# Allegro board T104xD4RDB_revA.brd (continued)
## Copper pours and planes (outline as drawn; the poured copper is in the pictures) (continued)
5V0_SLP on TOP (solid shape): 35.94,54.48 35.94,53.59 36.1,53.43 36.1,53.37 36.16,53.37 36.2,53.34 36.58,53.34 36.96,52.96 36.96,50.93 36.7,50.67 34.67,50.67 34.54,50.8 34.54,54.23 34.93,54.61 35.81,54.61
5V0_SLP on TOP (solid shape): 37.47,65.66 37.47,64.77 37.63,64.61 37.63,64.55 37.69,64.55 37.73,64.52 38.11,64.52 38.49,64.13 38.49,62.1 38.23,61.85 36.2,61.85 36.08,61.98 36.08,65.41 36.46,65.79 37.35,65.79
5V0_SLP on TOP (solid shape): 187.7,144.4 187.7,140.97 187.32,140.59 186.43,140.59 186.3,140.72 186.3,141.6 186.14,141.76 186.14,141.83 186.08,141.83 186.05,141.86 185.67,141.86 185.29,142.24 185.29,144.27 185.54,144.53 187.57,144.53
5V0_SLP on TOP (solid shape): 247.26,88.65 247.26,85.22 246.88,84.84 245.99,84.84 245.86,84.96 245.86,85.85 245.71,86.01 245.71,86.07 245.64,86.07 245.61,86.11 245.23,86.11 244.85,86.49 244.85,88.52 245.1,88.77 247.13,88.77
5V0_SLP on TOP (solid shape): 249.56,74.03 249.56,73.14 249.43,73.02 248.54,73.02 248.38,72.86 248.32,72.86 248.32,72.8 248.29,72.76 248.29,72.38 247.9,72 245.87,72 245.62,72.26 245.62,74.29 245.75,74.41 249.17,74.41
5V0_SLP on BOTTOM (solid shape): 30.94,165.76 30.94,165.23 30.98,165.01 31.12,164.82 31.12,162.06 30.86,161.81 29.97,161.81 29.46,161.3 29.46,159.9 29.08,159.52 26.54,159.52 26.29,159.77 26.29,161.63 26.68,161.79 26.85,162.19 26.85,165.51 27.41,166.07 30.63,166.07
5V0_SLP on BOTTOM (solid shape): 34.11,55.2 34.29,54.83 34.67,54.69 38,54.69 38.56,54.12 38.56,50.9 38.25,50.6 37.72,50.6 37.5,50.55 37.31,50.42 34.54,50.42 34.29,50.67 34.29,51.56 33.78,52.07 32.39,52.07 32,52.45 32,54.99 32.26,55.24 34.11,55.24
5V0_SLP on BOTTOM (solid shape): 35.64,66.37 35.82,66.01 36.2,65.86 39.53,65.86 40.09,65.3 40.09,62.08 39.78,61.77 39.25,61.77 39.03,61.73 38.84,61.59 36.08,61.59 35.82,61.85 35.82,62.74 35.31,63.25 33.92,63.25 33.54,63.63 33.54,66.17 33.79,66.42 35.64,66.42
5V0_SLP on BOTTOM (solid shape): 187.95,144.53 187.95,143.64 188.46,143.13 189.86,143.13 190.24,142.75 190.24,140.21 189.98,139.95 188.13,139.95 188.13,140 187.95,140.37 187.57,140.51 184.25,140.51 183.69,141.07 183.69,144.29 183.99,144.6 184.52,144.6 184.75,144.65 184.93,144.78 187.7,144.78
5V0_SLP on BOTTOM (solid shape): outline of 672 points within 199.77,70.4 261.37,147.32
5V0_SLP on TOP: 64.14,37.21 64.9,37.21 65.15,36.96 65.15,35.56 64.64,35.05 63.37,35.05 63.25,35.18 63.25,35.81 64.01,36.58 64.01,37.08
5V0_SLP on TOP: 5.59,50.8 8.89,50.8 9.53,50.16 9.53,40.64 8,39.12 6.6,39.12 6.48,39.24 6.48,40.89 5.08,42.29 5.08,50.29
5V0_SLP on TOP: 70.49,101.85 71.37,101.85 71.5,101.73 71.5,100.84 71.76,100.58 72.14,100.58 72.52,100.2 72.52,98.17 72.26,97.92 70.23,97.92 70.1,98.04 70.1,101.47
5V0_SLP on TOP: 33.4,36.32 36.7,36.32 36.96,36.58 36.96,44.07 36.45,44.58 33.4,44.58 33.15,44.32 33.15,36.58
5V0_SLP on TOP: 58.42,36.7 60.58,36.7 61.47,35.81 61.47,35.18 61.34,35.05 58.55,35.05 58.17,35.43 58.17,36.45
5V0_SLP on TOP: 20.83,72.39 21.46,71.75 21.46,60.33 20.7,59.56 11.81,59.56 11.18,60.2 11.18,71.88 11.68,72.39
5V0_SLP on BOTTOM: 6.35,42.67 20.32,42.67 20.96,43.31 20.96,71.5 20.32,72.14 6.48,72.14 6.1,71.75 6.1,42.93
5V0_SLP on BOTTOM: 67.82,102.49 69.6,102.49 70.1,101.98 73.03,101.98 74.17,100.84 74.17,98.17 73.66,97.66 70.23,97.66 69.85,98.04 69.85,98.93 69.47,99.31 67.95,99.31 67.56,99.69 67.56,102.23
5V0_SLP on L5PWR: 49.28,67.69 49.28,59.82 49.02,59.56 12.32,59.56 11.18,60.71 11.18,100.46 14.35,103.63 70.49,103.63 73.41,100.71 73.41,91.82
5V0_SLP on L6SIG: 20.83,72.64 37.47,72.64 40.26,69.85 40.26,48.01 41.53,46.74 49.34,46.74 55.44,40.64 64.26,40.64 67.82,37.08 67.82,27.56 72.64,22.73 72.64,19.05 72.01,18.42 64.01,18.42 59.44,22.99 59.44,33.27 57.91,34.8 54.1,34.8 48.01,40.89 6.48,40.89 5.08,42.29 5.08,164.21 29.72,188.85 201.42,188.85 206.5,183.77 206.5,146.69 205.36,145.54 192.47,145.54 190.31,143.38 190.31,139.83 189.55,139.06 184.28,139.06 183.64,139.7 183.64,148.72 185.8,150.88 191.71,150.88 195.58,154.75 195.58,172.85 191.9,176.53 50.67,176.53 42.16,168.02 42.16,163.7 19.3,140.84 19.3,74.17
5V0_SLP on L6SIG: 238.76,71.5 253.37,71.5 253.87,72.01 253.87,95.25 253.49,95.63 238.76,95.63 238.51,95.38 238.51,71.75
5V0_USB1 on TOP: 63.37,32.77 66.8,32.77 67.5,32.07 67.5,30.48 68.45,29.53 68.45,24 67.56,23.11 67.56,20.19 67.44,20.07 66.17,20.07 66.04,20.19 66.04,24.89 65.53,25.4 64.77,25.4 64.39,25.78 64.39,30.73 63.25,31.88 63.25,32.64
5V0_USB2 on TOP: 61.34,32.77 61.47,32.64 61.47,32 60.96,31.5 60.2,31.5 59.94,31.24 59.94,27.43 60.64,26.73 62.55,26.73 63.63,25.65 63.63,22.22 63.88,21.97 65.15,21.97 65.53,21.59 65.53,20.45 65.28,20.19 60.96,20.19 58.55,22.61 57.79,22.61 57.15,23.24 57.15,25.65 57.59,26.1 58.48,26.1 58.93,26.54 58.93,31.88 59.82,32.77
12V on TOP: 18.29,40.64 19.18,40.64 19.49,40.96 19.49,43.37 19.69,43.56 20.96,43.56 21.08,43.43 21.08,40.89 21.34,40.64 22.61,40.64 24.64,38.61 27.94,38.61 28.32,38.23 28.32,35.31 27.94,34.92 23.37,34.92 22.86,35.43 22.86,37.72 22.23,38.35 18.42,38.35 18.03,38.73 18.03,40.39
12V on TOP: 272.54,156.72 271.91,157.35 267.34,157.35 266.95,157.73 266.95,159.13 267.08,159.26 274.45,159.26 275.08,158.62 275.08,156.84 274.96,156.72
12V on TOP: 280.8,84.07 281.81,84.07 282.19,83.69 282.19,80.9 280.42,79.12 280.42,76.84 280.16,76.58 278.26,76.58 278,76.84 278,77.22 277.88,77.34 273.43,77.34 271.02,74.93 269.75,74.93 269.37,75.31 269.37,83.44 270,84.07 274.96,84.07 275.97,85.09 279.78,85.09
12V on TOP: 254.25,170.94 254.25,206.38 254.76,206.88 258.06,206.88 258.57,206.38 258.57,170.69 258.32,170.43 254.76,170.43
12V on BOTTOM: 21.84,37.97 23.5,36.32 26.42,36.32 26.92,36.83 26.92,76.84 21.21,82.55 21.21,173.86 35.05,187.71 249.3,187.71 254.25,182.75 254.25,167.39 265.68,155.96 265.68,85.22 271.78,79.12 282.07,79.12 282.96,80.01 282.96,84.33 282.7,84.58 280.8,84.58 280.42,84.96 276.73,84.96 275.46,86.23 274.19,86.23 273.3,87.12 273.3,157.73 260.86,170.18 260.86,187.71 252.86,195.71 30.73,195.71 14.99,179.96 14.99,80.52 21.84,73.66
12V_SLP on TOP: 61.47,82.55 61.6,82.68 62.23,82.68 62.48,82.93 62.48,83.57 62.36,83.69 60.33,83.69 60.07,83.44 60.07,81.66 60.2,81.53 61.34,81.53 61.47,81.66
12V_SLP on TOP: 25.65,49.02 27.94,46.74 27.94,40.39 27.69,40.13 24.89,40.13 24.64,40.39 24.64,42.55 23.24,43.94 16.76,43.94 15.88,43.05 12.19,43.05 11.68,43.56 11.68,46.74 12.45,47.5 14.61,47.5 16.13,49.02
12V_SLP on L3SIG: 26.54,44.45 26.54,41.91 26.92,41.53 39.24,41.53 40.01,42.29 54.1,42.29 58.17,46.35 58.17,77.72 61.98,81.53 61.98,82.8 61.6,83.19 58.42,83.19 55.25,80.01 55.25,66.55 53.59,64.9 53.59,63.37 55.12,61.85 55.12,57.15 52.58,54.61 52.58,47.24 49.78,44.45 40.13,44.45 39.37,45.21 27.31,45.21
12V_SLP on L6SIG: 60.2,82.93 61.47,82.93 61.72,82.68 61.72,81.79 61.34,81.41 60.58,81.41 60.07,81.91 60.07,82.8
AGND_SD1_PLL1 on L6SIG: 151.38,114.05 153.42,114.05 153.54,113.92 153.54,113.41 153.42,113.28 151.51,113.28 148.21,109.98 148.21,106.17 146.43,104.39 140.46,104.39 140.21,104.14 140.21,104.01 140.08,103.89 139.7,103.89 139.57,104.01 139.57,104.52 140.08,105.03 146.05,105.03 147.57,106.55 147.57,110.24
AGND_SD1_PLL2 on L6SIG: 152.4,117.86 153.42,117.86 153.54,117.73 153.54,117.22 153.42,117.09 152.53,117.09 146.56,111.12 146.56,107.7 146.05,107.19 144.02,107.19 143.64,107.57 141.16,107.57 141.03,107.7 140.53,107.7 140.34,107.51 140.34,107.31 140.21,107.19 139.83,107.19 139.7,107.31 139.7,107.7 140.08,108.08 145.67,108.08 145.92,108.33 145.92,111.38
AVDD_CGA1 on L5PWR: 122.81,99.95 127.25,99.95 127.51,99.69 128.14,99.69 128.27,99.57 128.27,99.19 128.14,99.06 127.64,99.06 127.25,98.68 126.24,98.68 125.48,97.92 122.81,97.92 122.56,98.17 122.56,99.69
AVDD_CGA2 on L5PWR: 122.68,101.6 128.02,101.6 128.27,101.35 128.27,100.08 128.14,99.95 127.64,99.95 127.38,100.2 122.81,100.2 122.56,100.46 122.56,101.47
AVDD_PLAT on L5PWR: 122.81,97.66 125.48,97.66 126.24,98.42 127.25,98.42 127.76,98.93 128.14,98.93 128.27,98.81 128.27,98.55 125.22,95.5 122.94,95.5 122.56,95.89 122.56,97.41
AVDD_SD1_PLL1 on L6SIG: 151.51,113.03 153.42,113.03 153.54,112.9 153.54,112.39 153.42,112.27 151.64,112.27 148.97,109.6 148.97,105.66 146.94,103.63 140.72,103.63 140.46,103.89 140.46,104.2 140.59,104.33 141.03,104.33 141.22,104.14 143.51,104.14 143.64,104.27 146.56,104.27 148.34,106.05 148.34,109.86
AVDD_SD1_PLL2 on L6SIG: 152.53,116.84 153.42,116.84 153.54,116.71 153.54,116.2 153.42,116.08 152.65,116.08 147.32,110.74 147.32,106.93 146.69,106.3 143.76,106.3 143.26,106.81 140.72,106.81 140.46,107.06 140.46,107.44 140.59,107.57 140.97,107.57 141.22,107.31 143.64,107.31 143.89,107.06 146.18,107.06 146.69,107.57 146.69,111
GND on TOP (solid shape): 178.69,89.66 178.69,86.11 178.44,85.85 177.91,85.85 177.67,85.9 177.44,85.85 176.91,85.85 176.66,86.11 176.66,89.53 176.91,89.79 178.56,89.79
GND on TOP (solid shape): 210.44,89.66 210.44,86.11 210.19,85.85 209.66,85.85 209.42,85.9 209.19,85.85 208.66,85.85 208.41,86.11 208.41,89.53 208.66,89.79 210.31,89.79
GND on TOP (solid shape): 42.93,55.24 42.93,46.1 42.16,45.34 35.05,45.34 34.64,45.75 34.64,46.83 34.54,46.83 34.54,48.13 34.67,48.26 36.96,48.26 37.72,47.5 40.51,47.5 41.02,48.01 41.02,51.56 40.51,52.07 37.72,52.07 37.47,52.32 37.47,52.96 36.83,53.59 36.75,53.59 36.7,53.65 36.4,53.65 36.32,53.72 36.32,54.99 36.96,55.63 42.55,55.63
GND on TOP (solid shape): 44.46,65.52 44.46,57.28 43.7,56.52 36.58,56.52 36.17,56.93 36.17,58.01 36.08,58.01 36.08,59.31 36.2,59.44 38.49,59.44 39.25,58.67 42.04,58.67 42.55,59.18 42.55,62.74 42.04,63.25 39.25,63.25 39,63.5 39,64.13 38.36,64.77 38.28,64.77 38.23,64.82 37.93,64.82 37.85,64.9 37.85,65.66 37.97,65.78 37.97,65.79 38.1,65.91 44.07,65.91
GND on TOP (solid shape): 187.6,149.45 187.6,148.37 187.7,148.37 187.7,147.07 187.57,146.94 185.29,146.94 184.52,147.7 181.73,147.7 181.22,147.19 181.22,143.64 181.73,143.13 184.52,143.13 184.78,142.88 184.78,142.24 185.41,141.6 185.49,141.6 185.54,141.55 185.85,141.55 185.92,141.48 185.92,140.72 185.8,140.6 185.8,140.59 185.67,140.46 179.71,140.46 179.32,140.85 179.32,149.1 180.08,149.86 187.19,149.86
GND on TOP (solid shape): 243.21,74.29 243.21,72 242.44,71.24 242.44,68.45 242.95,67.94 246.51,67.94 247.02,68.45 247.02,71.24 247.27,71.49 247.9,71.49 248.54,72.13 248.54,72.21 248.59,72.26 248.59,72.56 248.67,72.64 249.43,72.64 249.55,72.52 249.56,72.52 249.68,72.39 249.68,66.42 249.29,66.03 241.05,66.03 240.28,66.79 240.28,73.91 240.7,74.32 241.78,74.32 241.78,74.41 243.08,74.41
GND on TOP (solid shape): 247.17,93.69 247.17,92.62 247.26,92.62 247.26,91.31 247.13,91.19 244.85,91.19 244.09,91.95 241.29,91.95 240.78,91.44 240.78,87.88 241.29,87.38 244.09,87.38 244.34,87.12 244.34,86.49 244.98,85.85 245.05,85.85 245.1,85.8 245.41,85.8 245.48,85.72 245.48,84.96 245.36,84.84 245.36,84.84 245.24,84.71 239.27,84.71 238.88,85.1 238.88,93.34 239.64,94.11 246.75,94.11
GND on TOP (solid shape): outline of 256 points within 4.02,199.02 13.02,208.02
GND on TOP (solid shape): outline of 256 points within 4.02,11.52 13.02,20.52
GND on TOP (solid shape): outline of 256 points within 85.54,136.22 94.54,145.22
GND on TOP (solid shape): outline of 256 points within 139.02,199.02 148.02,208.02
GND on TOP (solid shape): outline of 256 points within 154,55.57 163,64.57
GND on TOP (solid shape): outline of 256 points within 274.02,199.02 283.02,208.02
GND on TOP (solid shape): outline of 256 points within 274.02,108.52 283.02,117.52
GND on BOTTOM (solid shape): 31.12,55.24 31.12,52.96 30.86,52.7 29.62,52.7 29.57,52.76 29.03,52.76 28.83,52.96 28.83,55.24 29.08,55.5 30.86,55.5
GND on BOTTOM (solid shape): 153.8,43.05 153.8,42.29 153.95,42.13 153.95,42.12 153.97,42.12 154.31,41.78 154.31,40.51 154.05,40.26 152.27,40.26 151.89,40.64 151.89,42.8 152.27,43.18 153.67,43.18
GND on BOTTOM (solid shape): 239.4,44.96 239.4,44.2 239.55,44.04 239.55,44.02 239.57,44.02 239.9,43.69 239.9,42.42 239.65,42.16 237.87,42.16 237.49,42.55 237.49,44.7 237.87,45.09 239.27,45.09
GND on BOTTOM (solid shape): 262.25,44.96 262.25,44.2 262.41,44.04 262.41,44.02 262.43,44.02 262.76,43.69 262.76,42.42 262.51,42.16 260.73,42.16 260.35,42.55 260.35,44.7 260.73,45.09 262.13,45.09
GND on BOTTOM (solid shape): 33.53,161.17 33.53,160.54 33.4,160.41 32.89,160.41 32.81,160.33 32.8,160.33 32.8,160.31 32.64,160.15 32.64,159.65 32.51,159.52 30.1,159.52 29.97,159.65 29.97,161.04 30.23,161.3 33.4,161.3
GND on BOTTOM (solid shape): 33.78,51.31 33.78,48.13 33.66,48.01 33.02,48.01 32.89,48.13 32.89,48.64 32.81,48.72 32.81,48.74 32.8,48.74 32.64,48.9 32.13,48.9 32,49.02 32,51.44 32.13,51.56 33.53,51.56
GND on BOTTOM (solid shape): 35.31,62.48 35.31,59.31 35.19,59.18 34.55,59.18 34.42,59.31 34.42,59.82 34.34,59.9 34.34,59.91 34.33,59.91 34.17,60.07 33.66,60.07 33.54,60.2 33.54,62.61 33.66,62.74 35.06,62.74
GND on BOTTOM (solid shape): 189.35,147.07 189.35,146.56 189.43,146.48 189.43,146.46 189.45,146.46 189.6,146.3 190.11,146.3 190.24,146.18 190.24,143.76 190.11,143.64 188.71,143.64 188.46,143.89 188.46,147.07 188.59,147.19 189.22,147.19
GND on BOTTOM (solid shape): 246.51,76.83 246.51,75.43 246.25,75.18 243.08,75.18 242.95,75.3 242.95,75.94 243.08,76.07 243.59,76.07 243.67,76.15 243.68,76.15 243.68,76.16 243.84,76.32 243.84,76.83 243.97,76.95 246.38,76.95
GND on BOTTOM (solid shape): 248.91,91.31 248.91,90.81 248.99,90.73 248.99,90.71 249.01,90.71 249.17,90.55 249.67,90.55 249.8,90.42 249.8,88.01 249.67,87.88 248.28,87.88 248.02,88.14 248.02,91.31 248.15,91.44 248.79,91.44
GND on BOTTOM (solid shape): 35.81,170.7 35.81,162.57 34.93,161.68 32.39,161.68 32.13,161.93 32.13,166.12 32.06,166.2 32.06,166.23 31.09,167.19 31.06,167.19 30.99,167.27 27.17,167.27 26.8,167.64 26.8,170.81 27.06,171.08 35.43,171.08
GND on BOTTOM (solid shape): 43.56,55.37 43.56,46.1 43.18,45.72 35.05,45.72 34.16,46.61 34.16,49.15 34.42,49.4 38.61,49.4 38.68,49.48 38.71,49.48 39.68,50.44 39.68,50.47 39.75,50.55 39.75,54.99 40.39,55.63 43.31,55.63
GND on BOTTOM (solid shape): 244.35,74.54 244.35,70.35 244.42,70.28 244.42,70.25 245.39,69.28 245.42,69.28 245.49,69.21 249.31,69.21 249.68,68.83 249.68,65.66 249.42,65.4 241.05,65.4 240.67,65.78 240.67,73.91 241.55,74.8 244.09,74.8
GND on BOTTOM (solid shape): 45.09,65.66 45.09,65.66 45.09,57.28 44.71,56.9 36.58,56.9 35.69,57.78 35.69,60.33 35.95,60.58 40.14,60.58 40.22,60.65 40.24,60.65 41.21,61.62 41.21,61.65 41.28,61.72 41.28,65.54 41.66,65.91 44.83,65.91
GND on BOTTOM (solid shape): 188.08,148.59 188.08,146.05 187.83,145.8 183.63,145.8 183.56,145.72 183.53,145.72 182.57,144.76 182.57,144.73 182.49,144.65 182.49,140.84 182.12,140.46 178.94,140.46 178.69,140.72 178.68,140.72 178.68,149.1 179.06,149.48 187.19,149.48
GND on BOTTOM (solid shape): 247.64,92.84 247.64,90.3 247.39,90.04 243.2,90.04 243.12,89.97 243.09,89.97 242.13,89 242.13,88.98 242.05,88.9 242.05,85.08 241.68,84.71 238.51,84.71 238.25,84.96 238.24,84.96 238.24,93.34 238.63,93.73 246.75,93.73
GND on BOTTOM (solid shape): 163.7,52.45 166.37,52.45 166.75,52.07 166.75,47.75 168.15,46.35 168.15,45.47 167.89,45.21 158.12,45.21 157.96,45.37 157.96,45.64 157.69,45.64 157.35,45.97 157.35,46.86 157.61,47.12 157.82,47.12 157.83,47.08 158.23,46.7 158.76,46.85 158.95,47.04 158.95,47.32 158.97,47.32 158.97,47.34 159.13,47.5 159.13,48.74 159.56,49.17 159.56,50.68 159.13,51.11 159.13,53.21 159.2,53.28 162.87,53.28
GND on BOTTOM (solid shape): 249.3,54.36 251.97,54.36 252.35,53.98 252.35,49.66 253.75,48.26 253.75,47.37 253.49,47.12 243.71,47.12 243.56,47.27 243.56,47.55 243.28,47.55 242.95,47.88 242.95,48.77 243.21,49.02 243.42,49.02 243.43,48.99 243.83,48.61 244.36,48.75 244.55,48.94 244.55,49.23 244.57,49.23 244.57,49.25 244.73,49.4 244.73,50.64 245.16,51.08 245.16,52.58 244.73,53.01 244.73,55.12 244.8,55.19 248.47,55.19
GND on BOTTOM (solid shape): 272.16,54.36 274.83,54.36 275.21,53.98 275.21,49.66 276.61,48.26 276.61,47.37 276.35,47.12 266.57,47.12 266.42,47.27 266.42,47.55 266.14,47.55 265.81,47.88 265.81,48.77 266.07,49.02 266.28,49.02 266.29,48.99 266.69,48.61 267.22,48.75 267.41,48.94 267.41,49.23 267.43,49.23 267.43,49.25 267.59,49.4 267.59,50.64 268.02,51.08 268.02,52.58 267.59,53.01 267.59,55.12 267.66,55.19 271.33,55.19
GND on BOTTOM (solid shape): outline of 256 points within 4.02,199.02 13.02,208.02
GND on BOTTOM (solid shape): outline of 256 points within 4.02,11.52 13.02,20.52
GND on BOTTOM (solid shape): outline of 256 points within 85.54,136.22 94.54,145.22
GND on BOTTOM (solid shape): outline of 256 points within 139.02,199.02 148.02,208.02
GND on BOTTOM (solid shape): outline of 256 points within 154,55.57 163,64.57
GND on BOTTOM (solid shape): outline of 256 points within 274.02,199.02 283.02,208.02
GND on BOTTOM (solid shape): outline of 256 points within 274.02,108.52 283.02,117.52
GND on BOTTOM (solid shape): outline of 424 points within 181.36,80.52 192.41,90.93
GND on BOTTOM (solid shape): outline of 424 points within 213.11,80.52 224.16,90.93
GND on TOP: 60.45,31.11 63.25,31.11 63.63,30.73 63.63,27.43 63.37,27.18 60.96,27.18 60.33,27.81 60.33,30.99
GND on TOP: 129.92,174.62 129.67,174.37 126.11,174.37 125.98,174.5 125.98,176.28 126.24,176.53 129.67,176.53 129.92,176.28
GND on TOP: outline of 135 points within 2.03,2.03 285,210
GND on TOP: 122.94,168.91 123.19,168.66 124.71,168.66 124.84,168.78 124.84,170.94 124.46,171.32 124.46,175.39 124.33,175.51 123.06,175.51 122.94,175.39
GND on TOP: 20.7,37.59 22.1,37.59 22.35,37.34 22.35,35.56 22.1,35.31 20.7,35.31 20.45,35.56 20.45,37.34
GND on TOP: 25.91,16.13 29.34,16.13 29.59,16.38 29.59,20.07 29.34,20.32 25.91,20.32 25.65,20.07 25.65,16.38
GND on TOP: 168.15,127.25 168.15,120.02 168.28,119.89 169.16,119.89 169.55,120.27 169.55,122.43 170.18,123.06 170.18,127.25 169.93,127.51 168.4,127.51
GND on TOP: 189.87,150.75 189.61,151 189.61,151.64 190.12,152.15 190.12,155.19 190.75,155.83 190.75,156.97 190.5,157.23 188.09,157.23 187.83,157.48 187.83,158.62 187.71,158.75 185.8,158.75 185.55,158.5 185.55,156.21 185.8,155.96 187.45,155.96 187.58,155.83 187.58,155.32 187.45,155.19 185.8,155.19 185.55,154.94 185.55,151.26 185.17,150.88 180.09,150.88 179.58,151.38 179.58,158.24 181.48,160.15 188.09,160.15 188.34,159.89 188.34,157.99 188.47,157.86 190.37,157.86 190.63,158.12 190.63,161.42 190.88,161.67 192.79,161.67 193.04,161.42 193.04,151.26 192.53,150.75
GND on TOP: 128.02,172.34 130.68,172.34 130.94,172.08 130.94,171.07 130.81,170.94 130.3,170.94 130.05,170.69 130.05,170.05 129.79,169.8 128.91,169.8 128.78,169.93 128.78,171.07 128.52,171.32 128.02,171.32 127.89,171.45 127.89,172.21
GND on TOP: 54.61,16.64 57.91,16.64 58.17,16.89 58.17,20.7 57.91,20.95 54.61,20.95 54.36,20.7 54.36,16.89
GND on TOP: 170.18,118.62 175.39,118.62 175.64,118.36 175.64,116.71 175.39,116.46 170.18,116.46 169.93,116.71 169.93,118.36
GND on TOP: 269.88,157.1 270.13,156.84 270.13,155.96 270.38,155.7 270.38,153.03 270.26,152.91 268.86,152.91 268.61,153.16 268.61,154.69 268.48,154.81 267.84,154.81 267.59,155.07 267.59,156.84 267.84,157.1
GND on TOP: 118.49,31.37 118.49,21.21 118.11,20.83 116.21,20.83 116.08,20.95 116.08,31.37 116.33,31.62 118.24,31.62
GND on TOP: 18.8,43.18 19.05,42.93 19.05,41.27 18.92,41.15 16.89,41.15 16.64,41.4 16.64,42.93 16.89,43.18
GND on TOP: 92.84,87.25 92.58,87.5 92.58,101.47 92.08,101.98 83.95,101.98 83.31,101.35 83.31,91.95 82.8,91.44 70.99,91.44 70.23,92.2 70.23,95.38 70.36,95.5 72.64,95.5 74.17,93.98 77.98,93.98 78.36,94.36 78.36,99.69 77.98,100.08 73.28,100.08 72.39,100.97 72.01,100.97 71.88,101.09 71.88,104.65 72.26,105.03 87.5,105.03 88.9,103.63 90.68,103.63 90.93,103.89 90.93,104.65 91.06,104.78 93.35,104.78 94.23,103.89 95,103.89 96.77,102.11 96.77,96.39 97.03,96.14 100.08,96.14 100.33,96.39 100.33,102.62 103.12,102.62 104.01,101.73 104.01,88.39 102.87,87.25
GND on TOP: 58.42,34.67 63.5,34.67 63.63,34.54 63.63,33.27 63.5,33.15 58.42,33.15 58.29,33.27 58.29,34.54
GND on TOP: 33.15,162.31 33.15,164.6 33.91,165.36 33.91,168.16 33.4,168.66 29.85,168.66 29.34,168.16 29.34,165.36 29.08,165.11 28.45,165.11 27.81,164.47 27.81,164.09 27.69,163.96 26.92,163.96 26.8,164.08 26.8,164.08 26.67,164.21 26.67,170.18 27.06,170.57 35.31,170.57 36.07,169.81 36.07,162.69 35.56,162.19 33.27,162.19
GND on TOP: 239.4,59.82 241.55,59.82 241.81,59.56 241.81,57.53 241.55,57.28 239.52,57.28 239.27,57.53 239.27,59.69
GND on TOP: 270.13,93.73 271.14,93.73 271.53,93.34 271.53,92.58 271.91,92.2 271.91,89.53 271.78,89.41 270.38,89.41 270,89.79 270,93.6
GND on TOP: 69.6,25.65 73.41,25.65 73.66,25.91 73.66,29.34 73.41,29.59 69.6,29.59 69.34,29.34 69.34,25.91
GND on BOTTOM: 45.34,134.87 79.63,134.87 79.88,134.62 79.88,133.22 79.63,132.97 45.47,132.97 45.21,133.22 45.21,134.75
GND on BOTTOM: 93.22,100.84 93.98,101.6 95.12,101.6 95.25,101.47 95.25,96.14 95.76,95.63 100.84,95.63 101.35,96.14 101.35,107.7 101.6,107.95 103.51,107.95 103.89,107.57 103.89,84.58 102.74,83.44 97.16,83.44 96.9,83.69 96.9,91.31 96.52,91.69 94.36,91.69 93.22,92.84
GND on BOTTOM: 67.69,98.81 69.09,98.81 69.34,98.55 69.34,95.38 69.22,95.25 68.58,95.25 68.45,95.38 68.45,96.01 68.2,96.27 67.69,96.27 67.56,96.39 67.56,98.68
GND on BOTTOM: 3.52,2.03 2.47,2.47 2.03,3.52 2.03,208.52 2.47,209.57 3.52,210 283.52,210 284.57,209.57 285,208.52 285,88.53 283.46,87 275.59,87 274.07,88.52 274.07,157.99 261.62,170.43 261.62,187.83 253.11,196.34 30.23,196.34 14.22,180.34 14.22,80.39 14.99,79.63 14.99,73.79 14.1,72.9 5.46,72.9 4.7,72.14 4.7,24.51 6.99,22.22 12.83,22.22 15.37,19.69 20.96,19.69 23.5,22.22 56.9,22.22 57.91,21.21 57.91,2.79 57.15,2.03
GND on BOTTOM: 124.33,52.96 125.35,51.94 126.75,51.94 127.25,51.44 127.25,47.37 127,47.12 122.68,47.12 122.43,47.37 122.43,52.45 122.94,52.96
GND on BOTTOM: 160.15,118.87 160.15,112.27 160.4,112.01 161.29,112.01 161.42,112.14 161.42,118.87 161.29,119 160.27,119
GND on BOTTOM: 142.37,60.96 143.38,59.94 144.65,59.94 145.16,59.44 145.16,55.37 144.91,55.12 140.97,55.12 140.34,55.75 140.34,60.58 140.72,60.96
GND on BOTTOM: 237.11,132.33 241.17,132.33 241.43,132.08 241.43,127.38 241.3,127.25 241.05,127.25 240.92,127.38 240.92,127.63 240.79,127.76 237.49,127.76 237.11,128.14 237.11,130.05 236.86,130.3 236.86,132.08
GND on BOTTOM: 165.99,112.01 166.12,112.14 166.12,119 165.99,119.13 165.48,119.13 165.35,119 165.35,112.14 165.48,112.01
GND on BOTTOM: 60.96,106.81 86.11,106.81 86.61,106.3 86.61,92.58 85.22,91.19 61.85,91.19 60.45,92.58 60.45,106.3 ; 1 cut-out
GND on L2GND: 3.52,2.03 2.47,2.47 2.03,3.52 2.03,208.52 2.47,209.57 3.52,210 283.52,210 284.57,209.57 285,208.52 285,29.86 284.23,29.08 238.89,29.08 236.28,31.69 236.28,36.77 234.57,38.48 230.89,38.48 230.12,39.24 172.47,39.24 169.99,36.77 169.99,32.58 167.26,29.84 154.94,29.84 149.86,34.92 149.86,39.12 148.59,40.39 134.62,40.39 133.22,38.99 133.22,35.05 132.46,34.29 119.51,34.29 118.75,33.53 118.75,21.46 123.57,16.64 123.57,7.37 120.9,4.7 109.86,4.7 107.95,6.6 107.95,17.14 106.3,18.8 100.58,18.8 92.96,11.18 92.96,7.62 92.71,7.37 83.44,7.37 83.06,7.75 83.06,11.3 81.66,12.7 81.66,16.38 80.01,18.03 73.79,18.03 73.15,17.4 73.15,11.05 72.14,10.03 65.91,10.03 65.15,10.8 65.15,17.27 64.39,18.03 60.33,18.03 59.44,17.14 59.44,2.67 58.8,2.03 ; 30 cut-outs
GND on L4PWR: 3.52,2.03 2.47,2.47 2.03,3.52 2.03,208.52 2.47,209.57 3.52,210 283.52,210 284.57,209.57 285,208.52 285,29.86 284.23,29.08 238.89,29.08 236.28,31.69 236.28,36.77 234.57,38.48 230.89,38.48 230.12,39.24 172.47,39.24 169.99,36.77 169.99,32.58 167.26,29.84 154.94,29.84 149.86,34.92 149.86,39.12 148.59,40.39 134.62,40.39 133.22,38.99 133.22,35.05 132.46,34.29 119.51,34.29 118.75,33.53 118.75,21.46 123.57,16.64 123.57,7.37 120.9,4.7 109.86,4.7 107.95,6.6 107.95,17.14 106.3,18.8 100.58,18.8 92.96,11.18 92.96,7.62 92.71,7.37 83.44,7.37 83.06,7.75 83.06,11.3 81.66,12.7 81.66,16.38 80.01,18.03 73.79,18.03 73.15,17.4 73.15,11.05 72.14,10.03 66.04,10.03 65.15,10.92 65.15,17.27 64.39,18.03 60.33,18.03 59.44,17.14 59.44,2.67 58.8,2.03 ; 1 cut-out
GND on L5PWR: 3.52,2.03 2.47,2.47 2.03,3.52 2.03,208.52 2.47,209.57 3.52,210 283.52,210 284.57,209.57 285,208.52 285,29.86 284.23,29.08 238.89,29.08 235.59,32.39 235.59,54.86 233.93,56.52 173.1,56.52 170.05,53.47 170.05,32.64 167.26,29.84 154.94,29.84 149.86,34.92 149.86,39.12 148.59,40.39 134.62,40.39 133.22,38.99 133.22,35.05 132.46,34.29 119.51,34.29 118.75,33.53 118.75,21.46 123.57,16.64 123.57,7.37 120.9,4.7 109.86,4.7 107.95,6.6 107.95,17.14 106.3,18.8 100.58,18.8 92.96,11.18 92.96,7.62 92.71,7.37 83.44,7.37 83.06,7.75 83.06,11.3 81.66,12.7 81.66,16.38 80.01,18.03 73.79,18.03 73.15,17.4 73.15,11.05 72.14,10.03 66.04,10.03 65.15,10.92 65.15,17.27 64.39,18.03 60.33,18.03 59.44,17.14 59.44,2.67 58.8,2.03 ; 1 cut-out
GND on L7GND: 3.52,2.03 2.47,2.47 2.03,3.52 2.03,208.52 2.47,209.57 3.52,210 283.52,210 284.57,209.57 285,208.52 285,29.86 284.23,29.08 238.89,29.08 235.59,32.39 235.59,54.86 233.93,56.52 173.1,56.52 170.05,53.47 170.05,32.64 167.26,29.84 154.94,29.84 149.86,34.92 149.86,39.12 148.59,40.39 134.62,40.39 133.22,38.99 133.22,35.05 132.46,34.29 119.51,34.29 118.75,33.53 118.75,21.46 123.57,16.64 123.57,7.37 120.9,4.7 109.86,4.7 107.95,6.6 107.95,17.14 106.3,18.8 100.58,18.8 92.96,11.18 92.96,7.62 92.71,7.37 83.44,7.37 83.06,7.75 83.06,11.3 81.66,12.7 81.66,16.38 80.01,18.03 73.79,18.03 73.15,17.4 73.15,11.05 72.14,10.03 65.91,10.03 65.15,10.8 65.15,17.27 64.39,18.03 60.33,18.03 59.44,17.14 59.44,2.67 58.8,2.03
SVDD on BOTTOM: 161.93,114.94 161.93,112.27 162.05,112.14 164.97,112.14 165.1,112.27 165.1,114.81 164.85,115.06 162.05,115.06
SVDD on L4PWR: 138.68,108.46 140.21,108.46 140.46,108.2 140.46,100.84 140.34,100.71 139.19,100.71 138.94,100.97 138.94,102.36 138.18,103.12 138.18,107.95
SVDD on L5PWR: 138.43,108.2 139.45,108.2 139.7,107.95 139.7,103.38 139.45,103.12 138.3,103.12 138.18,103.25 138.18,107.95
SVDD on L6SIG: 137.16,107.95 138.94,107.95 139.07,107.82 139.07,103.38 139.32,103.12 147.57,103.12 149.73,105.28 149.73,108.97 152.4,111.63 154.05,111.63 154.56,112.14 154.56,114.55 155.32,115.32 164.21,115.32 164.47,115.06 164.47,107.82 156.34,99.69 137.41,99.69 137.03,100.08 137.03,107.82
(no net) on TOP: 235.32,94.11 235.07,93.85 235.07,84.97 235.33,84.71 237.99,84.71 238.37,85.09 238.37,93.73 237.99,94.11
(no net) on TOP: 262.64,45.21 264.92,45.21 265.43,45.72 266.19,45.72 266.19,45.21 265.05,44.07 262.64,44.07 262.51,44.2 262.51,45.09
(no net) on TOP: 210.95,89.79 212.34,89.79 212.6,89.53 212.6,86.11 212.34,85.85 210.95,85.85 210.82,85.98 210.82,89.66
(no net) on TOP: 49.66,56.52 50.55,57.4 50.55,61.34 50.29,61.59 48.52,61.59 48.27,61.85 48.27,65.65 48.01,65.91 45.35,65.91 44.97,65.53 44.97,56.9 45.35,56.52
(no net) on TOP: 26.04,122.05 27.81,122.05 28.07,121.79 28.07,119.76 27.94,119.63 26.16,119.63 25.91,119.89 25.91,121.92
(no net) on TOP: 176.91,89.79 178.56,89.79 178.69,89.66 178.69,86.11 178.44,85.85 176.91,85.85 176.66,86.11 176.66,89.53
(no net) on TOP: 179.2,89.79 180.59,89.79 180.85,89.53 180.85,86.11 180.59,85.85 179.2,85.85 179.07,85.98 179.07,89.66
(no net) on TOP: 41.79,59.18 39.5,59.18 38.87,59.82 36.08,59.82 35.95,59.94 35.95,61.34 36.08,61.47 38.74,61.47 40.01,62.74 41.79,62.74 42.04,62.48 42.04,59.44
(no net) on TOP: 243.21,74.29 243.21,72 242.44,71.24 242.44,68.45 242.95,67.94 246.51,67.94 247.02,68.45 247.02,71.24 247.27,71.49 247.9,71.49 248.54,72.13 248.54,72.51 248.67,72.64 249.43,72.64 249.55,72.52 249.56,72.52 249.68,72.39 249.68,66.42 249.29,66.03 241.05,66.03 240.28,66.79 240.28,73.91 240.79,74.41 243.08,74.41
(no net) on TOP: 36.2,59.44 38.49,59.44 39.25,58.67 42.04,58.67 42.55,59.18 42.55,62.74 42.04,63.25 39.25,63.25 39,63.5 39,64.13 38.36,64.77 37.98,64.77 37.85,64.9 37.85,65.66 37.97,65.78 37.97,65.79 38.1,65.91 44.07,65.91 44.46,65.52 44.46,57.28 43.7,56.52 36.58,56.52 36.08,57.02 36.08,59.31
(no net) on TOP: 242.95,68.7 242.95,70.99 243.59,71.62 243.59,74.41 243.71,74.54 245.11,74.54 245.24,74.41 245.24,71.75 246.51,70.48 246.51,68.7 246.25,68.45 243.21,68.45
(no net) on TOP: 40.26,48.01 37.97,48.01 37.34,48.64 34.54,48.64 34.42,48.77 34.42,50.16 34.54,50.29 37.21,50.29 38.48,51.56 40.26,51.56 40.51,51.31 40.51,48.26
(no net) on TOP: 264.54,43.31 261.37,43.31 261.24,43.18 261.24,42.16 261.75,41.66 264.41,41.66 264.67,41.91 264.67,43.18
(no net) on TOP: 240.28,62.48 240.54,62.22 252.34,62.22 252.6,62.48 252.6,64.9 251.97,65.53 251.73,65.53 251.72,65.52 240.67,65.52 240.28,65.14
(no net) on TOP: 33.53,167.77 33.53,165.49 32.89,164.85 32.89,162.06 32.77,161.93 31.37,161.93 31.24,162.06 31.24,164.73 29.97,166 29.97,167.77 30.23,168.03 33.27,168.03
(no net) on TOP: 26.04,130.18 27.81,130.18 28.07,129.92 28.07,127.89 27.94,127.76 26.16,127.76 25.91,128.02 25.91,130.05
(no net) on TOP: 154.18,43.31 156.46,43.31 156.97,43.81 157.73,43.81 157.73,43.31 156.59,42.16 154.18,42.16 154.05,42.29 154.05,43.18
(no net) on TOP: 171.32,149.86 170.94,149.48 170.94,144.65 171.58,144.02 173.61,144.02 173.99,143.64 173.99,141.1 174.62,140.46 178.43,140.46 178.81,140.84 178.81,149.48 178.43,149.86
(no net) on TOP: 36.2,174 35.94,174.25 27.06,174.25 26.8,173.99 26.8,171.33 27.18,170.95 35.81,170.95 36.2,171.33
(no net) on TOP: 241.55,91.44 243.83,91.44 244.47,90.81 247.26,90.81 247.39,90.68 247.39,89.28 247.26,89.15 244.59,89.15 243.32,87.88 241.55,87.88 241.29,88.14 241.29,91.19
(no net) on TOP: 28.58,119.63 32.64,119.63 32.89,119.89 32.89,121.79 32.64,122.05 28.7,122.05 28.45,121.79 28.45,119.76
(no net) on TOP: 50.29,45.34 51.05,46.1 51.05,51.44 50.8,51.69 47.12,51.69 46.74,52.07 46.74,55.12 46.23,55.63 43.82,55.63 43.43,55.24 43.43,45.72 43.82,45.34
(no net) on TOP: 34.67,48.26 36.96,48.26 37.72,47.5 40.51,47.5 41.02,48.01 41.02,51.56 40.51,52.07 37.72,52.07 37.47,52.32 37.47,52.96 36.83,53.59 36.45,53.59 36.32,53.72 36.32,54.99 36.96,55.63 42.55,55.63 42.93,55.24 42.93,46.1 42.16,45.34 35.05,45.34 34.54,45.85 34.54,48.13
(no net) on TOP: 181.98,147.19 184.27,147.19 184.9,146.56 187.7,146.56 187.83,146.43 187.83,145.03 187.7,144.91 185.03,144.91 183.76,143.64 181.98,143.64 181.73,143.89 181.73,146.94
(no net) on TOP: 28.58,127.76 32.64,127.76 32.89,128.02 32.89,129.92 32.64,130.18 28.7,130.18 28.45,129.92 28.45,127.89
(no net) on TOP: 187.57,146.94 185.29,146.94 184.52,147.7 181.73,147.7 181.22,147.19 181.22,143.64 181.73,143.13 184.52,143.13 184.78,142.88 184.78,142.24 185.41,141.6 185.79,141.6 185.92,141.48 185.92,140.72 185.8,140.6 185.8,140.59 185.67,140.46 179.71,140.46 179.32,140.85 179.32,149.1 180.08,149.86 187.19,149.86 187.7,149.35 187.7,147.07
(no net) on TOP: 247.13,91.19 244.85,91.19 244.09,91.95 241.29,91.95 240.78,91.44 240.78,87.88 241.29,87.38 244.09,87.38 244.34,87.12 244.34,86.49 244.98,85.85 245.36,85.85 245.48,85.72 245.48,84.96 245.36,84.84 245.36,84.84 245.24,84.71 239.27,84.71 238.88,85.1 238.88,93.34 239.64,94.11 246.75,94.11 247.26,93.6 247.26,91.31
(no net) on TOP: 26.04,138.3 27.81,138.3 28.07,138.05 28.07,136.02 27.94,135.89 26.16,135.89 25.91,136.14 25.91,138.18
(no net) on TOP: 181.36,91.57 181.48,91.44 181.48,90.42 181.36,90.3 177.55,90.3 177.42,90.42 177.42,91.44 177.55,91.57
(no net) on TOP: 36.2,61.85 38.23,61.85 38.49,62.1 38.49,64.13 38.11,64.52 37.73,64.52 37.47,64.77 37.47,65.66 37.35,65.79 36.46,65.79 36.08,65.41 36.08,61.98
(no net) on TOP: 239.78,45.21 242.06,45.21 242.57,45.72 243.33,45.72 243.33,45.21 242.19,44.07 239.78,44.07 239.65,44.2 239.65,45.09
(no net) on TOP: 28.58,135.89 32.64,135.89 32.89,136.14 32.89,138.05 32.64,138.3 28.7,138.3 28.45,138.05 28.45,136.02
(no net) on TOP: 241.68,43.31 238.51,43.31 238.38,43.18 238.38,42.16 238.89,41.66 241.55,41.66 241.81,41.91 241.81,43.18
(no net) on TOP: 247.13,88.77 245.1,88.77 244.85,88.52 244.85,86.49 245.23,86.11 245.61,86.11 245.86,85.85 245.86,84.96 245.99,84.84 246.88,84.84 247.26,85.22 247.26,88.65
(no net) on TOP: 156.08,41.4 152.91,41.4 152.78,41.27 152.78,40.26 153.29,39.75 155.96,39.75 156.21,40.01 156.21,41.27
(no net) on TOP: 187.57,144.53 185.54,144.53 185.29,144.27 185.29,142.24 185.67,141.86 186.05,141.86 186.3,141.6 186.3,140.72 186.43,140.59 187.32,140.59 187.7,140.97 187.7,144.4
(no net) on TOP: 213.11,91.57 213.23,91.44 213.23,90.42 213.11,90.3 209.3,90.3 209.17,90.42 209.17,91.44 209.3,91.57
(no net) on TOP: 34.67,50.67 36.7,50.67 36.96,50.93 36.96,52.96 36.58,53.34 36.2,53.34 35.94,53.59 35.94,54.48 35.81,54.61 34.93,54.61 34.54,54.23 34.54,50.8
(no net) on TOP: 30.86,162.19 30.86,164.22 30.61,164.47 28.58,164.47 28.19,164.09 28.19,163.71 27.94,163.46 27.05,163.46 26.92,163.33 26.92,162.44 27.31,162.06 30.73,162.06
(no net) on TOP: 208.66,89.79 210.31,89.79 210.44,89.66 210.44,86.11 210.19,85.85 208.66,85.85 208.41,86.11 208.41,89.53
(no net) on TOP: 245.62,74.29 245.62,72.26 245.87,72 247.9,72 248.29,72.38 248.29,72.76 248.54,73.02 249.43,73.02 249.56,73.14 249.56,74.03 249.17,74.41 245.75,74.41
(no net) on BOTTOM: 240.28,43.56 240.28,41.91 240.54,41.66 249.81,41.66 252.6,44.45 252.6,46.23 252.22,46.61 244.6,46.61 243.52,45.53 243.52,44.77 242.57,43.81 240.54,43.81
(no net) on BOTTOM: 182.49,140.84 182.49,144.65 183.63,145.8 187.83,145.8 188.08,146.05 188.08,148.59 187.19,149.48 179.06,149.48 178.68,149.1 178.68,140.72 178.69,140.72 178.94,140.46 182.12,140.46
(no net) on BOTTOM: 224.16,82.3 224.03,82.17 222.76,82.17 222.12,82.8 216.66,82.8 216.54,82.93 214.88,82.93 214.5,82.55 214.5,80.77 214.25,80.52 213.36,80.52 213.11,80.77 213.11,89.15 214.88,90.93 223.01,90.93 224.16,89.79
(no net) on BOTTOM: 239.27,45.09 239.4,44.96 239.4,44.2 239.9,43.69 239.9,42.42 239.65,42.16 237.87,42.16 237.49,42.55 237.49,44.7 237.87,45.09
(no net) on BOTTOM: 187.95,143.64 187.95,144.53 187.7,144.78 183.89,144.78 183.63,144.53 183.63,141.1 184.4,140.34 187.7,140.34 188.08,139.95 189.98,139.95 190.24,140.21 190.24,142.75 189.86,143.13 188.46,143.13
(no net) on BOTTOM: 29.97,161.81 30.86,161.81 31.12,162.06 31.12,165.87 30.86,166.12 27.43,166.12 26.67,165.36 26.67,162.06 26.29,161.68 26.29,159.77 26.54,159.52 29.08,159.52 29.46,159.9 29.46,161.3
(no net) on BOTTOM: 263.14,43.56 263.14,41.91 263.4,41.66 272.67,41.66 275.46,44.45 275.46,46.23 275.08,46.61 267.46,46.61 266.38,45.53 266.38,44.77 265.43,43.81 263.4,43.81
(no net) on BOTTOM: 33.53,161.17 33.53,160.54 33.4,160.41 32.89,160.41 32.64,160.15 32.64,159.65 32.51,159.52 30.1,159.52 29.97,159.65 29.97,161.04 30.23,161.3 33.4,161.3
(no net) on BOTTOM: 262.13,45.09 262.25,44.96 262.25,44.2 262.76,43.69 262.76,42.42 262.51,42.16 260.73,42.16 260.35,42.55 260.35,44.7 260.73,45.09
(no net) on BOTTOM: 237.36,93.73 235.32,93.73 234.94,93.34 234.94,84.96 234.95,84.96 235.2,84.71 237.48,84.71 237.74,84.96 237.74,93.34
(no net) on BOTTOM: 242.05,85.08 242.05,88.9 243.2,90.04 247.39,90.04 247.64,90.3 247.64,92.84 246.75,93.73 238.63,93.73 238.24,93.34 238.24,84.96 238.25,84.96 238.51,84.71 241.68,84.71
(no net) on BOTTOM: 242.95,75.3 242.95,75.94 243.08,76.07 243.59,76.07 243.84,76.32 243.84,76.83 243.97,76.95 246.38,76.95 246.51,76.83 246.51,75.43 246.25,75.18 243.08,75.18
(no net) on BOTTOM: 27.17,167.27 30.99,167.27 32.13,166.12 32.13,161.93 32.39,161.68 34.93,161.68 35.81,162.57 35.81,170.7 35.43,171.08 27.05,171.08 27.05,171.07 26.8,170.81 26.8,167.64
(no net) on BOTTOM: 44.45,45.72 46.48,45.72 46.86,46.1 46.86,55.24 46.48,55.63 44.32,55.63 44.07,55.37 44.07,46.1
(no net) on BOTTOM: 177.79,149.48 175.76,149.48 175.38,149.1 175.38,140.72 175.39,140.72 175.64,140.46 177.92,140.46 178.17,140.72 178.17,149.1
(no net) on BOTTOM: 33.66,48.01 33.02,48.01 32.89,48.13 32.89,48.64 32.64,48.9 32.13,48.9 32,49.02 32,51.44 32.13,51.56 33.53,51.56 33.78,51.31 33.78,48.13
(no net) on BOTTOM: 188.59,147.19 189.22,147.19 189.35,147.07 189.35,146.56 189.6,146.3 190.11,146.3 190.24,146.18 190.24,143.76 190.11,143.64 188.71,143.64 188.46,143.89 188.46,147.07
(no net) on BOTTOM: 153.67,43.18 153.8,43.05 153.8,42.29 154.31,41.78 154.31,40.51 154.05,40.26 152.27,40.26 151.89,40.64 151.89,42.8 152.27,43.18
(no net) on BOTTOM: 34.29,51.56 34.29,50.67 34.54,50.42 38.35,50.42 38.61,50.67 38.61,54.1 37.85,54.86 34.54,54.86 34.16,55.24 32.26,55.24 32,54.99 32,52.45 32.39,52.07 33.78,52.07
(no net) on BOTTOM: 192.41,82.3 192.28,82.17 191.01,82.17 190.37,82.8 184.91,82.8 184.79,82.93 183.13,82.93 182.75,82.55 182.75,80.77 182.5,80.52 181.61,80.52 181.36,80.77 181.36,89.15 183.13,90.93 191.26,90.93 192.41,89.79
(no net) on BOTTOM: 45.98,56.9 48.01,56.9 48.39,57.28 48.39,65.66 48.39,65.66 48.13,65.91 45.85,65.91 45.6,65.66 45.6,57.28
(no net) on BOTTOM: 249.31,69.21 245.49,69.21 244.35,70.35 244.35,74.54 244.09,74.8 241.55,74.8 240.67,73.91 240.67,65.78 241.05,65.4 249.43,65.4 249.43,65.41 249.68,65.66 249.68,68.83
(no net) on BOTTOM: 243.71,47.12 253.49,47.12 253.75,47.37 253.75,48.26 252.35,49.66 252.35,53.98 251.97,54.36 249.3,54.36 248.41,55.24 244.86,55.24 244.73,55.12 244.73,49.4 244.35,49.02 243.21,49.02 242.95,48.77 242.95,47.88
(no net) on BOTTOM: 245.62,70.35 245.36,70.6 245.36,74.41 245.62,74.67 246.51,74.67 247.02,75.18 247.02,76.57 247.4,76.95 247.4,76.96 247.71,77.28 247.71,84.13 247.26,84.58 243.96,84.58 243.2,85.34 243.2,88.77 243.45,89.03 247.26,89.03 247.52,88.77 247.52,87.88 248.02,87.38 249.42,87.38 250.06,86.74 253.24,86.74 253.75,87.25 253.75,104.39 243.97,114.17 225.43,114.17 217.68,121.92 204.22,121.92 199.77,126.36 199.77,146.94 200.15,147.32 205.87,147.32 206.88,146.3 206.88,131.57 210.19,128.27 222,128.27 228.47,121.79 248.29,121.79 261.37,108.71 261.37,82.93 253.24,74.8 250.19,74.8 250.19,74.8 249.81,74.41 249.81,71.11 249.05,70.35
(no net) on BOTTOM: 41.28,65.54 41.28,61.72 40.14,60.58 35.95,60.58 35.69,60.33 35.69,57.78 36.58,56.9 44.71,56.9 45.09,57.28 45.09,65.66 45.09,65.66 44.83,65.91 41.66,65.91
(no net) on BOTTOM: 35.81,171.97 35.81,174 35.43,174.38 27.05,174.38 27.05,174.37 26.8,174.12 26.8,171.84 27.05,171.58 35.43,171.58
(no net) on BOTTOM: 35.82,62.74 35.82,61.85 36.08,61.59 39.89,61.59 40.14,61.85 40.14,65.28 39.38,66.04 36.08,66.04 35.69,66.42 33.79,66.42 33.54,66.17 33.54,63.63 33.92,63.25 35.31,63.25
(no net) on BOTTOM: 248.15,91.44 248.79,91.44 248.91,91.31 248.91,90.81 249.17,90.55 249.67,90.55 249.8,90.42 249.8,88.01 249.67,87.88 248.28,87.88 248.02,88.14 248.02,91.31
(no net) on BOTTOM: 39.75,54.99 39.75,50.55 38.61,49.4 34.42,49.4 34.16,49.15 34.16,46.61 35.05,45.72 43.18,45.72 43.56,46.1 43.56,55.37 43.31,55.63 40.39,55.63
(no net) on BOTTOM: 35.19,59.18 34.55,59.18 34.42,59.31 34.42,59.82 34.17,60.07 33.66,60.07 33.54,60.2 33.54,62.61 33.66,62.74 35.06,62.74 35.31,62.48 35.31,59.31
(no net) on BOTTOM: 28.83,55.24 28.83,52.96 29.08,52.7 30.86,52.7 31.12,52.96 31.12,55.24 30.86,55.5 29.08,55.5
(no net) on BOTTOM: 154.69,41.66 154.69,40.01 154.94,39.75 164.21,39.75 167.01,42.55 167.01,44.32 166.62,44.7 159,44.7 157.92,43.62 157.92,42.86 156.97,41.91 154.94,41.91
(no net) on BOTTOM: 240.67,64.51 240.67,62.48 241.05,62.1 249.43,62.1 249.43,62.1 249.68,62.36 249.68,64.64 249.43,64.89 241.05,64.89
(no net) on BOTTOM: 266.57,47.12 276.35,47.12 276.61,47.37 276.61,48.26 275.21,49.66 275.21,53.98 274.83,54.36 272.16,54.36 271.27,55.24 267.72,55.24 267.59,55.12 267.59,49.4 267.21,49.02 266.07,49.02 265.81,48.77 265.81,47.88
(no net) on BOTTOM: 158.12,45.21 167.89,45.21 168.15,45.47 168.15,46.35 166.75,47.75 166.75,52.07 166.37,52.45 163.7,52.45 162.81,53.34 159.26,53.34 159.13,53.21 159.13,47.5 158.75,47.12 157.61,47.12 157.35,46.86 157.35,45.97
(no net) on L3SIG: 180.21,91.31 191.01,91.31 193.29,89.03 193.29,81.15 192.53,80.39 189.74,80.39 189.48,80.64 185.55,80.64 185.17,81.03 182.5,81.03 179.96,83.57 179.96,91.06
(no net) on L6SIG: 209.55,82.93 221.11,82.93 221.62,82.42 221.62,79.63 221.23,79.25 209.55,79.25 209.17,79.63 209.17,82.55
(no net) on L6SIG: 177.8,82.93 189.36,82.93 189.87,82.42 189.87,79.63 189.48,79.25 177.8,79.25 177.42,79.63 177.42,82.55
EARTH on TOP (solid shape): outline of 256 points within 274.02,4.02 283.02,13.02
EARTH on BOTTOM (solid shape): outline of 256 points within 274.02,4.02 283.02,13.02
EARTH on TOP: outline of 98 points within 60.2,2.03 285,21.21
EARTH on BOTTOM: outline of 90 points within 60.2,2.03 285,21.21
EARTH on L2GND, L4PWR: 60.83,2.03 60.2,2.67 60.2,16.89 60.58,17.27 64.01,17.27 64.39,16.89 64.39,10.41 65.53,9.27 72.77,9.27 73.66,10.16 73.66,16.76 74.17,17.27 79.63,17.27 80.9,16 80.9,12.45 82.3,11.05 82.3,7.24 82.93,6.6 93.09,6.6 93.73,7.24 93.73,10.8 100.97,18.03 106.05,18.03 107.19,16.89 107.19,6.22 109.47,3.94 121.29,3.94 124.33,6.98 124.33,16.76 119.51,21.59 119.51,32.13 119.89,32.51 133.35,32.51 134.37,33.53 134.37,38.1 134.87,38.61 147.96,38.61 148.46,38.1 148.46,33.91 154.31,28.07 167.64,28.07 171.58,32 171.58,36.19 172.85,37.47 229.74,37.47 230.5,36.7 233.93,36.7 234.76,35.88 234.76,30.29 237.74,27.3 284.23,27.3 285,26.53 285,3.52 284.57,2.47 283.52,2.03 282.96,2.03
EARTH on L5PWR, L7GND: 60.83,2.03 60.2,2.67 60.2,16.89 60.58,17.27 64.01,17.27 64.39,16.89 64.39,10.41 65.53,9.27 72.77,9.27 73.66,10.16 73.66,16.76 74.17,17.27 79.63,17.27 80.9,16 80.9,12.45 82.3,11.05 82.3,7.24 82.93,6.6 93.09,6.6 93.73,7.24 93.73,10.8 100.97,18.03 106.05,18.03 107.19,16.89 107.19,6.22 109.47,3.94 121.29,3.94 124.33,6.98 124.33,16.76 119.51,21.59 119.51,32.13 119.89,32.51 133.35,32.51 134.37,33.53 134.37,38.1 134.87,38.61 147.96,38.61 148.46,38.1 148.46,33.91 154.31,28.07 167.64,28.07 171.58,32 171.58,53.21 173.48,55.12 233.43,55.12 234.06,54.48 234.06,30.99 237.74,27.3 284.23,27.3 285,26.53 285,3.52 284.57,2.47 283.52,2.03 282.96,2.03
EVDD on TOP: 41.15,148.08 43.82,148.08 44.2,147.7 44.2,141.86 43.94,141.6 41.78,141.6 41.02,142.37 41.02,144.15 41.53,144.65 41.53,146.3 41.02,146.81 41.02,147.95
EVDD on BOTTOM: 72.77,76.96 71.37,78.36 38.23,78.36 32,84.58 32,139.7 37.08,144.78 43.69,144.78 43.94,144.53 43.94,142.24 43.31,141.6 40.13,141.6 35.31,136.78 35.31,91.06 37.08,89.28 37.08,84.07 40.51,80.64 73.28,80.64 75.06,78.87 75.06,77.34 74.68,76.96
EVDD on L3SIG: 73.41,79.12 78.49,79.12 81.15,76.45 81.15,68.96 63.37,51.18 63.37,43.94 57.02,37.59 46.1,37.59 45.59,38.1 45.59,40.39 46.23,41.02 54.86,41.02 59.69,45.85 59.69,53.21 77.47,70.99 77.47,73.15 76.96,73.66 74.68,73.66 73.03,75.31 73.03,78.74
EVDD on L4PWR: 131.45,96.9 131.7,96.65 131.7,92.84 132.21,92.33 132.21,82.42 120.9,71.12 73.15,71.12 72.9,71.37 72.9,78.23 73.53,78.87 77.47,78.87 82.3,74.04 103.51,74.04 114.3,84.84 128.65,84.84 129.41,85.6 129.41,88.52 129.03,88.9 129.03,97.28 129.29,97.54 131.19,97.54 131.45,97.28
EVDD on L6SIG: 47.37,40.51 47.75,40.13 47.75,38.61 47.12,37.97 30.23,37.97 25.02,32.77 19.94,32.77 19.56,33.15 19.56,34.8 19.94,35.18 23.5,35.18 28.83,40.51
VCORE on TOP: 96.27,107.7 99.44,107.7 99.82,107.31 99.82,96.77 99.57,96.52 97.28,96.52 97.16,96.65 97.16,106.43 96.9,106.68 96.14,106.68 96.01,106.81 96.01,107.44
VCORE on BOTTOM: 96.01,107.95 100.46,107.95 100.84,107.57 100.84,96.27 100.58,96.01 96.01,96.01 95.76,96.27 95.76,107.7
VCORE on L3SIG: 124.33,104.65 126.11,104.65 126.37,104.39 128.27,104.39 128.52,104.65 131.19,104.65 131.45,104.39 131.45,103.89 131.32,103.76 130.94,103.76 130.81,103.63 130.81,103.25 130.68,103.12 128.4,103.12 128.14,102.87 124.21,102.87 123.95,103.12 123.95,104.27
VCORE on L4PWR: 137.54,107.7 137.92,107.31 137.92,103 138.68,102.23 138.68,100.84 139.07,100.46 140.34,100.46 140.46,100.33 140.46,96.9 140.21,96.65 139.07,96.65 138.81,96.9 138.81,97.16 138.43,97.54 132.08,97.54 131.45,98.17 124.71,98.17 122.3,95.76 119,95.76 117.73,94.49 117.73,92.33 117.48,92.08 98.55,92.08 96.77,93.85 96.77,107.44 97.03,107.7
VCORE on L5PWR: 130.56,107.57 137.67,107.57 137.92,107.31 137.92,103.12 138.18,102.87 140.21,102.87 140.46,102.62 140.46,96.9 140.08,96.52 139.19,96.52 139.07,96.65 139.07,101.35 138.68,101.73 130.43,101.73 130.18,101.98 130.18,107.19
VCORE_SLP on TOP: 84.46,86.74 84.46,83.57 84.71,83.31 95,83.31 95.38,83.69 95.38,86.49 95,86.87 84.58,86.87
VCORE_SLP on BOTTOM: 88.77,107.95 94.87,107.95 95.25,107.57 95.25,102.36 94.87,101.98 93.85,101.98 92.84,100.97 92.84,92.71 94.36,91.19 96.14,91.19 96.27,91.06 96.27,83.69 96.01,83.44 89.28,83.44 87.12,85.6 87.12,106.3
VCORE_SLP on L5PWR: 130.3,101.47 138.56,101.47 138.81,101.22 138.81,85.22 134.87,81.28 89.79,81.28 89.41,81.66 89.41,89.28 90.04,89.92 131.06,89.92 131.45,90.3 131.45,94.49 132.84,95.89 132.84,98.17 131.83,99.19 130.18,99.19 130.05,99.31 130.05,101.22
VPP on TOP: 185.55,169.42 188.98,169.42 190.12,168.28 190.12,158.37 189.87,158.12 188.85,158.12 188.72,158.24 188.72,160.27 188.47,160.53 185.67,160.53 185.29,160.91 185.29,169.16
VTT on TOP: 126.37,173.99 130.94,173.99 131.19,173.74 131.19,172.72 131.06,172.59 126.49,172.59 126.24,172.85 125.86,172.85 125.86,173.48
VTT on TOP: 127.25,169.29 127.25,168.78 124.97,166.5 124.97,163.7 125.35,163.32 125.35,160.15 125.98,159.51 126.37,159.51 126.49,159.64 126.49,161.29 126.87,161.67 127.64,161.67 128.02,161.29 128.02,159.64 128.27,159.38 129.29,159.38 129.41,159.51 129.41,161.04 129.67,161.29 131.19,161.29 131.45,161.04 131.45,160.53 132.08,160.53 132.08,161.54 130.94,162.69 130.94,167.77 130.05,168.66 130.05,169.29 129.92,169.42 129.29,169.42 129.16,169.29 129.16,168.91 129.03,168.78 128.14,168.78 128.02,168.91 128.02,169.29 127.89,169.42 127.38,169.42
VTT on BOTTOM: 126.11,174.37 130.94,174.37 131.57,173.74 131.57,168.66 130.68,167.77 130.68,161.42 130.56,161.29 125.22,161.29 124.97,161.54 124.97,173.23
XVDD on BOTTOM: 161.93,118.87 161.93,116.08 162.05,115.95 164.85,115.95 165.1,116.2 165.1,118.75 164.85,119 162.05,119
XVDD on L4PWR: 140.97,108.2 140.97,100.58 140.72,100.33 140.72,97.03 140.97,96.77 149.48,96.77 164.47,111.76 164.47,118.62 164.34,118.75 156.21,118.75 145.92,108.46 141.22,108.46
XVDD on L5PWR: 141.22,108.33 142.75,108.33 142.88,108.2 142.88,97.54 142.62,97.28 141.22,97.28 140.97,97.54 140.97,108.08
N16909680 on TOP (solid shape): 157.43,43.8 157.73,43.8 157.73,43.31 156.59,42.16 154.18,42.16 154.05,42.29 154.05,43.18 154.18,43.31 156.46,43.31 156.96,43.8 157.4,43.8
N17246863 on TOP: 74.8,18.16 76.2,18.16 76.45,18.42 76.45,19.81 76.2,20.07 74.68,20.07 74.55,19.94 74.55,18.42
N17246863 on BOTTOM: 73.03,19.3 75.95,19.3 76.2,19.05 76.2,18.42 75.95,18.16 73.79,18.16 72.9,17.27 72.9,11.43 72.39,10.92 71.37,10.92 70.74,11.56 70.74,17.02
N17251651 on TOP (solid shape): 184.9,146.56 185.28,146.56 185.28,146.55 187.71,146.55 187.83,146.43 187.83,145.03 187.7,144.91 185.03,144.91 183.76,143.64 181.98,143.64 181.73,143.89 181.73,146.94 181.98,147.19 184.27,147.19
N17251739 on TOP (solid shape): 42.04,62.48 42.04,59.44 41.79,59.18 39.5,59.18 38.87,59.82 38.49,59.82 38.49,59.83 36.07,59.83 35.95,59.94 35.95,61.34 36.08,61.47 38.74,61.47 40.01,62.74 41.79,62.74
N17251826 on TOP (solid shape): 40.51,51.31 40.51,48.26 40.26,48.01 37.97,48.01 37.34,48.64 36.96,48.64 36.96,48.65 34.54,48.65 34.42,48.77 34.42,50.16 34.54,50.29 37.21,50.29 38.48,51.56 40.26,51.56
N17251915 on TOP (solid shape): 245.24,74.41 245.24,71.75 246.51,70.48 246.51,68.7 246.25,68.45 243.21,68.45 242.95,68.7 242.95,70.99 243.59,71.62 243.59,72 243.59,72 243.59,74.42 243.71,74.54 245.11,74.54
N17252002 on TOP (solid shape): 33.53,167.77 33.53,165.49 32.89,164.85 32.89,164.48 32.88,164.48 32.88,162.05 32.77,161.93 31.37,161.93 31.24,162.06 31.24,164.73 29.97,166 29.97,167.77 30.23,168.03 33.27,168.03
N17526505 on TOP: 70.1,97.54 72.77,97.54 74.55,99.31 77.34,99.31 77.6,99.06 77.6,94.87 77.34,94.61 74.17,94.61 72.9,95.89 70.1,95.89 69.98,96.01 69.98,97.41
N17526513 on TOP: 83.69,101.22 83.69,91.82 84.46,91.06 84.46,88.27 85.22,87.5 92.08,87.5 92.2,87.63 92.2,101.22 91.82,101.6 84.07,101.6
N17588927 on TOP: 119.76,46.86 119.76,45.09 119.89,44.96 120.52,44.96 122.17,46.61 122.17,47.24 122.05,47.37 120.27,47.37
N17590523 on TOP: 139.07,55.37 139.95,55.37 140.08,55.24 140.08,54.61 138.43,52.96 137.92,52.96 137.67,53.21 137.67,54.48 138.3,55.12 138.81,55.12
N17596715 on TOP: 63.25,84.84 63.25,76.71 63.5,76.45 64.9,76.45 65.41,76.96 65.41,79.5 65.91,80.01 65.91,84.07 65.02,84.96 63.37,84.96
N18200448 on TOP (solid shape): 243.03,45.7 243.33,45.7 243.33,45.21 242.19,44.07 239.78,44.07 239.65,44.2 239.65,45.09 239.78,45.21 242.06,45.21 242.56,45.71 243,45.71
N18205399 on TOP (solid shape): 265.89,45.7 266.19,45.7 266.19,45.21 265.05,44.07 262.64,44.07 262.51,44.2 262.51,45.09 262.64,45.21 264.92,45.21 265.42,45.71 265.86,45.71
N18280045 on TOP (solid shape): 244.47,90.81 244.84,90.81 244.84,90.8 247.27,90.8 247.39,90.68 247.39,89.28 247.26,89.15 244.59,89.15 243.32,87.88 241.55,87.88 241.29,88.14 241.29,91.19 241.55,91.44 243.83,91.44

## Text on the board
Ref Des/Silkscreen Top: BACKCTL | BACKLIGHT | FLIP | PNLFMT | ON/OFF | COP | RESET | CPLD_JTAG | EVDD | 3.3V | 0 | 1 | CPU_FAN | FA_VDD | PROG_SFP | PROG_MTR | ASLEEP | PROFIBUS | PWR | SD_VDD_SEL | <-> | DVI_SEL | SYS_FAN1 | SYS_FAN2 | SYS_FAN3 | SYS_FAN4 | VER.A
NCLEGEND-1-8: FIGURE | SIZE | 10.0 | 16.0 | 19.69 | 25.59 | 27.56 | 29.13 | 33.0 | 35.43 | 39.37 | 43.31 | 45.0 | 47.0 | 51.18 | 53.15 | 55.12 | 62.99 | 90.55 | 96.46 | 120.0 | 125.98 | 133.86 | 57.0 | 59.06 | 61.02 | 92.52 | 96.06 | 127.95 | 146.06 | 157.48 | 96.46x47.24 | DRILL CHART: TOP to BOTTOM | ALL UNITS ARE IN MILS | TOLERANCE | +0.0/-0.0 | +2.0/-2.0 | +3.0/-3.0 | PLATED | NON-PLATED | QTY | 3561 | 278 | 64 | 288 | 36 | 7 | 2 | 16 | 127 | 59 | 40 | 4 | 18 | 20 | 14 | 6 | 8 | 1
